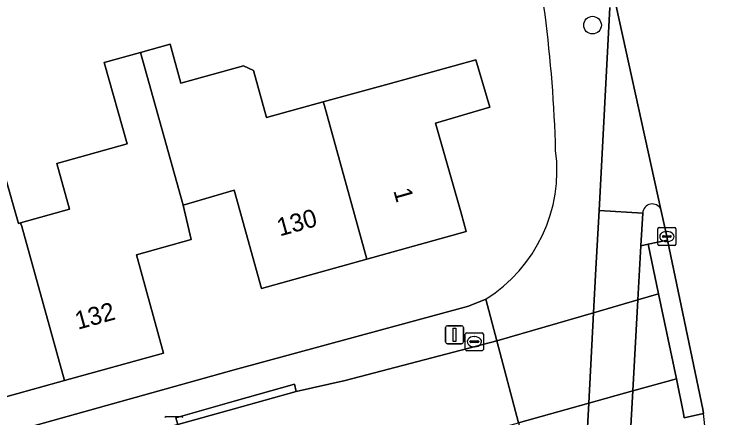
# Model space of a CAD drawing. Extents: x 159626 to 160723, y 388173 to 389416.
# Drawn here: x 159987.78 to 160026.77, y 388288.7 to 388311.16 of the extents above; entities that cross this region are included whole.
import ezdxf

# ---------------------------------------------------------------- set-up
doc = ezdxf.new("R2010")
doc.units = 0
for name, color, linetype in [('IMGEO_Boom', 7, 'Continuous'), ('IMGEO_Erf', 7, 'Continuous'), ('IMGEO_Fietspad_open', 7, 'Continuous'), ('IMGEO_Kolk', 7, 'Continuous'), ('IMGEO_Lichtmast', 7, 'Continuous'), ('IMGEO_Pand', 7, 'Continuous'), ('IMGEO_Pand_nummerreeks', 7, 'Continuous'), ('IMGEO_Rijbaan_lokaal_gesloten', 7, 'Continuous'), ('IMGEO_Rijbaan_lokaal_open', 7, 'Continuous'), ('IMGEO_Verkeerseiland_open', 7, 'Continuous'), ('IMGEO_Voetpad_open', 7, 'Continuous')]:
    doc.layers.add(name, color=color, linetype=linetype)

msp = doc.modelspace()

# ---------------------------------------------------------------- linework, layer by layer
at = {"layer": 'IMGEO_Boom'}
msp.add_circle((160019.911, 388310.54), 0.489, dxfattribs=at)
at = {"layer": 'IMGEO_Erf'}
for points in [[(159987.273, 388302.183), (159988.021, 388299.517), (159988.146, 388299.552), (159990.864, 388300.306), (159990.161, 388302.841), (159994.054, 388303.933), (159992.789, 388308.46), (159994.804, 388309.019), (159996.443, 388309.473), (159997.044, 388307.318), (160000.527, 388308.277), (160001.083, 388308.018), (160001.802, 388305.408), (160004.953, 388306.276), (160008.617, 388307.285), (160013.437, 388308.612), (160014.199, 388305.976), (160011.18, 388305.097), (160012.623, 388300.025), (160012.897, 388299.063), (160007.383, 388297.526), (160001.526, 388295.893), (160000, 388301.371), (159997.177, 388300.534), (159997.608, 388298.617), (159994.572, 388297.775), (159996.087, 388292.311), (159990.581, 388290.784), (159984.705, 388289.154)], [(159893.644, 388261.656), (159940.482, 388274.742), (160000, 388291.371), (160013.03, 388294.925), (160013.985, 388295.31)]]:
    msp.add_lwpolyline(points, dxfattribs=at)
for centre, radius, start, end in [((159941.49, 388301.435), 76.402, 1.60005, 12.98204), ((160009.476, 388302.466), 8.458, 302.2166, 7.4848)]:
    msp.add_arc(centre, radius, start, end, dxfattribs=at)
at = {"layer": 'IMGEO_Fietspad_open'}
for points in [[(160023.709, 388300.3), (160020.694, 388314.057)], [(160020.866, 388311.513), (160020.27, 388300.229), (160022.699, 388300.094)], [(160022.149, 388290.208), (160019.705, 388289.527), (160019.579, 388287.147), (160019.315, 388281.813), (160019.313, 388280.785), (160019.381, 388280.018), (160020.117, 388276.986)], [(160021.692, 388282.003), (160022.149, 388290.208)]]:
    msp.add_lwpolyline(points, dxfattribs=at)
for points in [[(160022.598, 388298.275), (160022.699, 388300.094), (160020.27, 388300.229), (160020.099, 388297), (160019.97, 388294.557), (160022.431, 388295.272)], [(160022.431, 388295.272), (160019.97, 388294.557), (160019.705, 388289.527), (160022.149, 388290.208)]]:
    msp.add_lwpolyline(points, close=True, dxfattribs=at)
msp.add_arc((160023.231, 388300.066), 0.532, 26.0228, 177.0331, dxfattribs=at)
at = {"layer": 'IMGEO_Kolk'}
for p, q in [((160023.541, 388298.362), (160023.541, 388299.214)), ((160023.616, 388299.288), (160024.468, 388299.288)), ((160024.542, 388299.214), (160024.542, 388298.362)), ((160023.8, 388298.782), (160023.8, 388298.794)), ((160023.843, 388298.831), (160024.241, 388298.831)), ((160024.029, 388299.068), (160024.054, 388299.068)), ((160024.284, 388298.794), (160024.284, 388298.782)), ((160024.238, 388298.745), (160023.84, 388298.745)), ((160024.052, 388298.508), (160024.027, 388298.508)), ((160024.468, 388298.288), (160023.616, 388298.288)), ((160012.845, 388292.519), (160012.845, 388293.371)), ((160012.92, 388293.445), (160013.772, 388293.445)), ((160013.846, 388293.371), (160013.846, 388292.519)), ((160013.104, 388292.939), (160013.104, 388292.951)), ((160013.147, 388292.988), (160013.545, 388292.988)), ((160013.333, 388293.225), (160013.358, 388293.225)), ((160013.588, 388292.951), (160013.588, 388292.939)), ((160013.542, 388292.902), (160013.144, 388292.902)), ((160013.356, 388292.665), (160013.331, 388292.665)), ((160013.772, 388292.445), (160012.92, 388292.445)), ((159996.233, 388288.778), (159997.085, 388288.778))]:
    msp.add_line(p, q, dxfattribs=at)
for points in [[(160023.541, 388298.362), (160023.541, 388299.214)], [(160023.616, 388299.288), (160024.468, 388299.288)], [(160024.542, 388299.214), (160024.542, 388298.362)], [(160024.468, 388298.288), (160023.616, 388298.288)], [(160012.845, 388292.519), (160012.845, 388293.371)], [(160012.92, 388293.445), (160013.772, 388293.445)], [(160013.846, 388293.371), (160013.846, 388292.519)], [(160013.772, 388292.445), (160012.92, 388292.445)], [(159996.233, 388288.778), (159997.085, 388288.778)]]:
    msp.add_lwpolyline(points, dxfattribs=at)
for centre, radius, start, end in [((160023.618, 388299.212), 0.0765, 91.552, 178.448), ((160023.618, 388299.212), 0.0765, 91.552, 178.448), ((160024.466, 388299.212), 0.0765, 1.552, 88.448), ((160024.466, 388299.212), 0.0765, 1.552, 88.448), ((160023.84, 388298.791), 0.0403, 85.8775, 175.7526), ((160024.245, 388298.793), 0.0386, 1.7309, 96.639), ((160023.837, 388298.781), 0.0366, 178.938, 274.7102), ((160024.241, 388298.788), 0.043, 264.8664, 352.4533), ((160023.618, 388298.364), 0.0765, 181.552, 268.448), ((160023.618, 388298.364), 0.0765, 181.552, 268.448), ((160024.466, 388298.364), 0.0765, 271.552, 358.448), ((160024.466, 388298.364), 0.0765, 271.552, 358.448), ((160012.922, 388293.369), 0.0765, 91.552, 178.448), ((160012.922, 388293.369), 0.0765, 91.552, 178.448), ((160013.77, 388293.369), 0.0765, 1.552, 88.448), ((160013.77, 388293.369), 0.0765, 1.552, 88.448), ((160013.144, 388292.948), 0.0403, 85.8775, 175.7526), ((160013.549, 388292.95), 0.0386, 1.7309, 96.639), ((160013.141, 388292.938), 0.0366, 178.938, 274.7102), ((160013.545, 388292.945), 0.043, 264.8664, 352.4533), ((160012.922, 388292.521), 0.0765, 181.552, 268.448), ((160012.922, 388292.521), 0.0765, 181.552, 268.448), ((160013.77, 388292.521), 0.0765, 271.552, 358.448), ((160013.77, 388292.521), 0.0765, 271.552, 358.448), ((159996.235, 388288.702), 0.0765, 91.552, 178.448), ((159996.235, 388288.702), 0.0765, 91.552, 178.448), ((159997.083, 388288.702), 0.0765, 1.552, 88.448), ((159997.083, 388288.702), 0.0765, 1.552, 88.448)]:
    msp.add_arc(centre, radius, start, end, dxfattribs=at)
for centre, major_axis, ratio, start_param, end_param in [((160024.028, 388298.788), (-0.387, 0.002), 0.722429, 4.712389, 7.853982), ((160024.053, 388298.788), (-0.39, 0.002), 0.717154, 1.570796, 4.712389), ((160013.332, 388292.945), (-0.387, 0.002), 0.722429, 4.712389, 7.853982), ((160013.357, 388292.945), (-0.39, 0.002), 0.717154, 1.570796, 4.712389)]:
    msp.add_ellipse(centre, major_axis=major_axis, ratio=ratio, start_param=start_param, end_param=end_param, dxfattribs=at)
at = {"layer": 'IMGEO_Lichtmast'}
for p, q in [((160011.75, 388292.93), (160011.75, 388293.73)), ((160011.75, 388293.73), (160011.75, 388292.93)), ((160011.85, 388293.83), (160012.64, 388293.83)), ((160012.64, 388293.83), (160011.85, 388293.83)), ((160012.74, 388293.73), (160012.74, 388292.93)), ((160012.74, 388292.93), (160012.74, 388293.73)), ((160012.64, 388292.83), (160011.85, 388292.83)), ((160011.85, 388292.83), (160012.64, 388292.83))]:
    msp.add_line(p, q, dxfattribs=at)
msp.add_lwpolyline([(160012.17, 388293.705), (160012.32, 388293.705), (160012.32, 388292.955), (160012.17, 388292.955), (160012.17, 388293.705)], dxfattribs=at)
for centre, start, end in [((160011.85, 388293.73), 90, 180), ((160011.85, 388293.73), 90, 180), ((160012.64, 388293.73), 0, 90), ((160012.64, 388293.73), 360, 90), ((160011.85, 388292.93), 180, 270), ((160011.85, 388292.93), 180, 270), ((160012.64, 388292.93), 270, 0), ((160012.64, 388292.93), 270, 0)]:
    msp.add_arc(centre, 0.1, start, end, dxfattribs=at)
at = {"layer": 'IMGEO_Pand'}
for points in [[(160005.014, 388306.062), (160004.953, 388306.276), (160001.802, 388305.408), (160001.083, 388308.018), (160000.527, 388308.277), (159997.044, 388307.318), (159996.443, 388309.473), (159994.804, 388309.019), (159997.177, 388300.534), (160000, 388301.371), (160001.526, 388295.893), (160007.383, 388297.526)], [(159990.581, 388290.784), (159996.087, 388292.311), (159994.572, 388297.775), (159997.608, 388298.617), (159997.177, 388300.534), (159994.804, 388309.019), (159992.789, 388308.46), (159994.054, 388303.933), (159990.161, 388302.841), (159990.864, 388300.306), (159988.146, 388299.552), (159988.207, 388299.34)], [(160007.383, 388297.526), (160012.897, 388299.063), (160012.623, 388300.025), (160011.18, 388305.097), (160014.199, 388305.976), (160013.437, 388308.612), (160008.617, 388307.285), (160004.953, 388306.276), (160005.014, 388306.062)], [(159980.373, 388293.792), (159983.202, 388294.577), (159983.731, 388292.669), (159984.705, 388289.154), (159990.581, 388290.784), (159988.207, 388299.34), (159988.146, 388299.552), (159988.021, 388299.517), (159987.273, 388302.183), (159982.449, 388300.83), (159981.753, 388303.314), (159978.001, 388302.263)]]:
    msp.add_lwpolyline(points, close=True, dxfattribs=at)
at = {"layer": 'IMGEO_Rijbaan_lokaal_gesloten'}
msp.add_lwpolyline([(160032.543, 388301.251), (160032.232, 388302.091), (160027.287, 388316.662), (160026.183, 388320.536), (160019.347, 388319.41), (160020.694, 388314.057), (160023.709, 388300.3), (160024.04, 388298.788), (160024.077, 388298.593), (160026.043, 388289.19), (160026.077, 388288.953)], dxfattribs=at)
msp.add_arc((160014.135, 388287.396), 12.043, 316.0602, 7.4309, dxfattribs=at)
at = {"layer": 'IMGEO_Rijbaan_lokaal_open'}
msp.add_lwpolyline([(159942.447, 388267.928), (159942.469, 388267.934), (159961.24, 388273.152), (160000, 388283.967), (160000.787, 388284.187), (160013.445, 388287.791), (160015.391, 388288.325), (160015.802, 388288.44), (160014.596, 388292.994), (160006.167, 388290.779), (160003.456, 388290.183), (160000, 388289.214), (159996.875, 388288.337), (159986.316, 388285.375), (159979.756, 388283.534), (159968.71, 388280.435), (159965.037, 388279.403), (159941.069, 388272.705), (159898.585, 388260.761)], dxfattribs=at)
at = {"layer": 'IMGEO_Verkeerseiland_open'}
for points in [[(160022.699, 388300.094), (160022.598, 388298.275), (160023.002, 388298.362), (160024.077, 388298.593), (160024.04, 388298.788), (160023.709, 388300.3)], [(160024.566, 388290.881), (160022.149, 388290.208), (160021.692, 388282.003)], [(160026.077, 388288.953), (160025.001, 388288.721), (160024.968, 388288.959), (160024.566, 388290.881)]]:
    msp.add_lwpolyline(points, dxfattribs=at)
msp.add_lwpolyline([(160024.077, 388298.593), (160023.002, 388298.362), (160023.578, 388295.606), (160024.566, 388290.881), (160024.968, 388288.959), (160025.001, 388288.721), (160026.077, 388288.953), (160026.043, 388289.19)], close=True, dxfattribs=at)
for centre, radius, start, end in [((160023.231, 388300.066), 0.532, 26.0228, 177.0331), ((160014.135, 388287.396), 12.043, 316.0602, 7.4309)]:
    msp.add_arc(centre, radius, start, end, dxfattribs=at)
at = {"layer": 'IMGEO_Voetpad_open'}
for points in [[(160013.985, 388295.31), (160014.596, 388292.994), (160019.97, 388294.557), (160020.099, 388297), (160020.27, 388300.229), (160020.866, 388311.513)], [(160014.596, 388292.994), (160013.985, 388295.31), (160013.03, 388294.925), (160000, 388291.371), (159940.482, 388274.742), (159893.644, 388261.656), (159890.751, 388260.859), (159859.945, 388252.179), (159854.746, 388250.727), (159853.266, 388250.313), (159853.151, 388250.281), (159853.021, 388250.711), (159850.494, 388250), (159845.138, 388248.493), (159844.644, 388248.354), (159842.921, 388247.869), (159839.772, 388246.983), (159784.145, 388231.332), (159767.275, 388225.855), (159755.968, 388222.214)], [(159898.585, 388260.761), (159941.069, 388272.705), (159965.037, 388279.403), (159964.938, 388279.853), (159968.589, 388280.864), (159968.71, 388280.435), (159979.756, 388283.534), (159979.667, 388283.956), (159986.208, 388285.785), (159986.316, 388285.375), (159996.875, 388288.337), (159996.762, 388288.715), (160000, 388289.63), (160003.348, 388290.576), (160003.456, 388290.183), (160006.167, 388290.779), (160014.596, 388292.994)]]:
    msp.add_lwpolyline(points, dxfattribs=at)
for points in [[(160023.002, 388298.362), (160022.598, 388298.275), (160022.431, 388295.272), (160023.578, 388295.606)], [(160023.578, 388295.606), (160022.431, 388295.272), (160022.149, 388290.208), (160024.566, 388290.881)], [(160019.97, 388294.557), (160014.596, 388292.994), (160015.802, 388288.44), (160019.705, 388289.527)], [(159996.875, 388288.337), (160000, 388289.214), (160003.456, 388290.183), (160003.348, 388290.576), (160000, 388289.63), (159996.762, 388288.715)], [(160019.705, 388289.527), (160015.802, 388288.44), (160016.393, 388286.257), (160019.579, 388287.147)]]:
    msp.add_lwpolyline(points, close=True, dxfattribs=at)
for centre, radius, start, end in [((159941.49, 388301.435), 76.402, 1.60005, 12.98204), ((160009.476, 388302.466), 8.458, 302.2166, 7.4848)]:
    msp.add_arc(centre, radius, start, end, dxfattribs=at)

# ---------------------------------------------------------------- texts
at = {"layer": 'IMGEO_Pand_nummerreeks'}
for s, rotation, p in [('1', 285.8839, (160008.839, 388301.337)), ('130', 15.5787, (160002.542, 388298.792)), ('132', 15.5023, (159991.325, 388293.605))]:
    msp.add_text(s, height=1, rotation=rotation, dxfattribs=at).set_placement(p)

doc.saveas('drawing.dxf')
